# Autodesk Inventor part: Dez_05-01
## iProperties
Created: 2005-12
Part Number: Dez_05-01
Document SubType Name: Modeling
Designer: W. Holzwarth
Author: W. Holzwarth
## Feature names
1. Trennen3
2. Trennen4
3. Spiegeln1 [Mirror]
4. Rundung1 [Fillet]
5. Runde Anordnung2 [Circular Pattern]
6. Drehung2 [Revolution]
7. Rundung2 [Fillet]
8. Bohrung1 [Hole]
